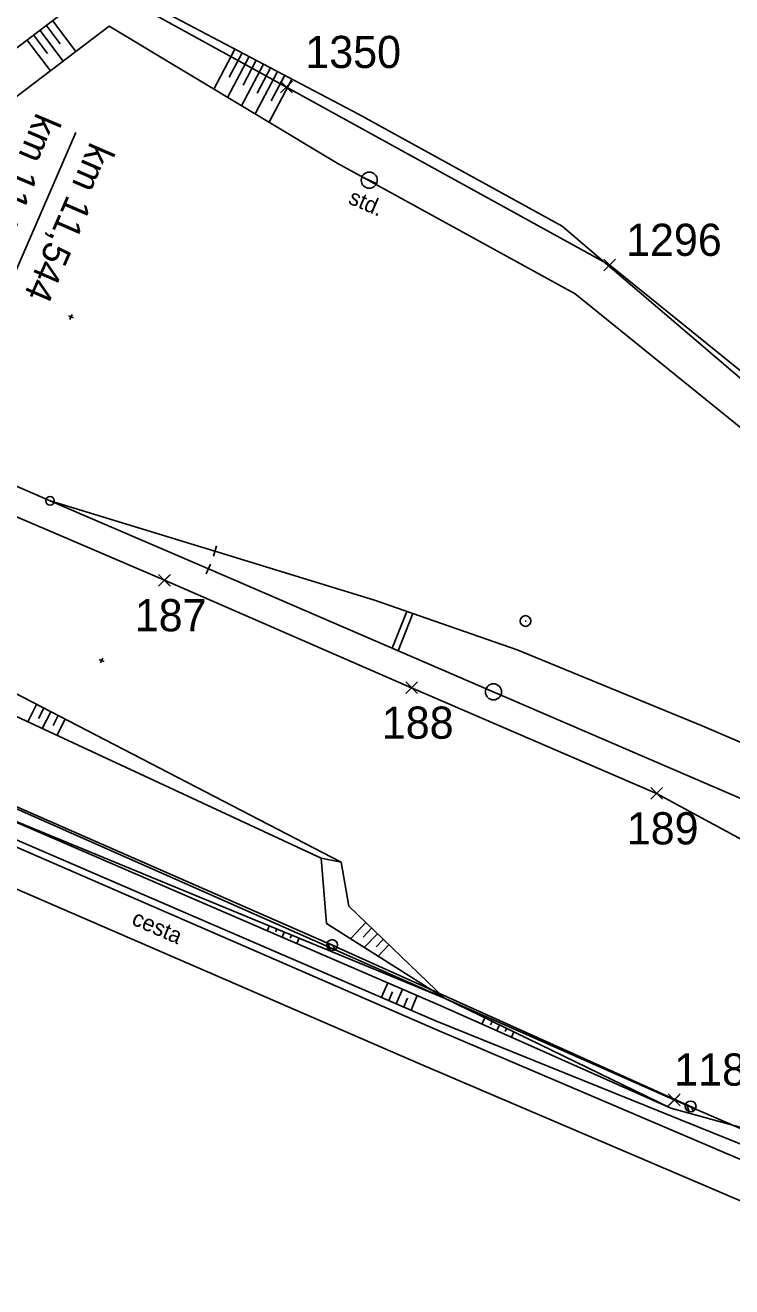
# Model space of a CAD drawing. Extents: x -866402 to -860377, y -1041908 to -1038598.
# Drawn here: x -861070.2 to -861004.3, y -1040160.6 to -1040043.1 of the extents above; entities that cross this region are included whole.
import ezdxf

# ---------------------------------------------------------------- set-up
doc = ezdxf.new("R2010")
doc.units = 0
for name, color, linetype in [('PS 02 trasa', 7, 'Continuous'), ('SZDC', 7, 'Continuous'), ('Vrstva 1', 7, 'Continuous'), ('Vrstva 2', 7, 'Continuous'), ('Vrstva 25', 7, 'Continuous'), ('Vrstva 36', 7, 'Continuous'), ('Vrstva 41', 7, 'Continuous'), ('Vrstva 48', 7, 'Continuous'), ('Vrstva 49', 7, 'Continuous'), ('Vrstva 5', 7, 'Continuous'), ('Vrstva 51', 7, 'Continuous'), ('Vrstva 60', 7, 'Continuous'), ('Vrstva 7', 7, 'Continuous'), ('Vrstva 9', 7, 'Continuous')]:
    doc.layers.add(name, color=color, linetype=linetype)

msp = doc.modelspace()

# ---------------------------------------------------------------- linework, layer by layer
at = {"layer": 'PS 02 trasa'}
msp.add_lwpolyline([(-861275.08, -1039976.7), (-861256.92, -1039992.44), (-861236.93, -1040007.63), (-861216.04, -1040021.56), (-861194.33, -1040033.85), (-861171.81, -1040045.14), (-861147.59, -1040055.88), (-861141.51, -1040058.52), (-861134.42, -1040061.82), (-861125.95, -1040065.2), (-861103.13, -1040075.05), (-861080.22, -1040084.95), (-861057.2, -1040094.8), (-861034.16, -1040104.82), (-861011.32, -1040114.66), (-860987.72, -1040127.44), (-860941.72, -1040147.22), (-860915.57, -1040159.23)], dxfattribs=at)
at = {"layer": 'SZDC'}
for points in [[(-860979.92, -1040156.1), (-861009.68, -1040143.23), (-861085.36, -1040109.77), (-861149.67, -1040082.68), (-861135.92, -1040065.09), (-861147.11, -1040058.58), (-861187.17, -1040040.97), (-861209.35, -1040028.85), (-861227.63, -1040016.54), (-861229.18, -1040015.49), (-861234.59, -1040011.85), (-861236.71, -1040010.09), (-861295.08, -1039961.46)], [(-861261.75, -1039976.4), (-861207.66, -1040016.44), (-861178.07, -1040032.92), (-861123.93, -1040056.86), (-861120.81, -1040053.41), (-861111.29, -1040057.53), (-861106.75, -1040059.49), (-861091.91, -1040065.91), (-861080.02, -1040037.82), (-861096.96, -1040029.84), (-861063.4, -1040039.15), (-861045.83, -1040048.83), (-861015.69, -1040065.42), (-860995.26, -1040081.93), (-860925.73, -1040118.15), (-860902.64, -1040130.18), (-860914.76, -1040137.1), (-860798.14, -1040185.35)]]:
    msp.add_lwpolyline(points, dxfattribs=at)
at = {"layer": 'Vrstva 1'}
msp.add_line((-861067.87, -1040087.39), (-861052.5, -1040092.08), dxfattribs=at)
for points in [[(-861077.48, -1040083.24), (-861076.39, -1040083.71), (-861067.87, -1040087.39), (-861053.11, -1040093.75)], [(-861052.5, -1040092.08), (-861037.62, -1040096.65), (-861024.33, -1040101.3), (-861007.06, -1040108.36), (-860979.17, -1040120.32), (-860937.59, -1040138.29), (-860889.45, -1040159.06)], [(-861053.11, -1040093.75), (-861027.49, -1040104.79), (-860981.18, -1040124.75), (-860939.74, -1040142.64), (-860923.59, -1040149.61), (-860920.27, -1040151.05), (-860891.33, -1040163.55), (-860835.4, -1040187.75)]]:
    msp.add_lwpolyline(points, dxfattribs=at)
at = {"layer": 'Vrstva 2'}
for p, q in [((-861067.87, -1040087.39), (-861052.5, -1040092.08)), ((-861052.35, -1040091.6), (-861052.64, -1040092.56)), ((-861052.91, -1040093.29), (-861053.31, -1040094.21))]:
    msp.add_line(p, q, dxfattribs=at)
msp.add_lwpolyline([(-861077.48, -1040083.24), (-861076.39, -1040083.71), (-861067.87, -1040087.39), (-861053.11, -1040093.75)], dxfattribs=at)
msp.add_circle((-861067.87, -1040087.39), 0.4, dxfattribs=at)
at = {"layer": 'Vrstva 25'}
msp.add_lwpolyline([(-861109.11, -1040099.06), (-861074.55, -1040114.35), (-861041.57, -1040128.8), (-861008.15, -1040143.84)], dxfattribs=at)
at = {"layer": 'Vrstva 36'}
for p, q in [((-861042.03, -1040128.6), (-861041.11, -1040129.01)), ((-861041.11, -1040129.01), (-861042.03, -1040128.6)), ((-861041.72, -1040129.28), (-861041.97, -1040128.63)), ((-861041.33, -1040129.24), (-861041.48, -1040128.84)), ((-861008.61, -1040143.63), (-861007.69, -1040144.05)), ((-861007.69, -1040144.05), (-861008.61, -1040143.63)), ((-861008.29, -1040144.32), (-861008.54, -1040143.66)), ((-861007.91, -1040144.28), (-861008.06, -1040143.88))]:
    msp.add_line(p, q, dxfattribs=at)
for centre in [(-861041.57, -1040128.8), (-861008.15, -1040143.84)]:
    msp.add_circle(centre, 0.503, dxfattribs=at)
for centre in [(-861041.57, -1040128.8), (-861008.15, -1040143.84)]:
    msp.add_arc(centre, 0.503, 155.7777, 335.7777, dxfattribs=at)
at = {"layer": 'Vrstva 41'}
msp.add_line((-861038.8, -1040057.21), (-861037.42, -1040057.81), dxfattribs=at)
msp.add_circle((-861038.11, -1040057.51), 0.752, dxfattribs=at)
at = {"layer": 'Vrstva 48'}
for p, q in [((-861066.64, -1040046.41), (-861068.83, -1040043.53)), ((-861066.92, -1040044.81), (-861068.23, -1040043.08)), ((-861065.45, -1040045.51), (-861067.63, -1040042.63)), ((-861067.84, -1040047.32), (-861070.02, -1040044.44)), ((-861068.11, -1040045.71), (-861069.42, -1040043.98)), ((-861052.6, -1040049.02), (-861050.63, -1040045.29)), ((-861051.31, -1040049.8), (-861049.31, -1040045.99)), ((-861051.16, -1040047.9), (-861049.97, -1040045.64)), ((-861050.03, -1040050.57), (-861047.98, -1040046.69)), ((-861049.86, -1040048.65), (-861048.64, -1040046.34)), ((-861048.56, -1040049.39), (-861047.32, -1040047.04)), ((-861048.74, -1040051.34), (-861046.65, -1040047.39)), ((-861047.45, -1040052.12), (-861045.33, -1040048.09)), ((-861047.25, -1040050.13), (-861045.99, -1040047.74)), ((-861069.95, -1040107.99), (-861069.12, -1040106.38)), ((-861068.95, -1040107.68), (-861068.46, -1040106.73)), ((-861068.59, -1040108.62), (-861067.79, -1040107.07)), ((-861067.59, -1040108.33), (-861067.12, -1040107.42)), ((-861067.23, -1040109.26), (-861066.46, -1040107.76)), ((-861047.61, -1040127.47), (-861047.43, -1040127.02)), ((-861039.86, -1040128.21), (-861038.43, -1040126.71)), ((-861046.85, -1040127.58), (-861046.73, -1040127.31)), ((-861046.23, -1040128.06), (-861046.04, -1040127.59)), ((-861045.47, -1040128.17), (-861045.35, -1040127.88)), ((-861044.86, -1040128.66), (-861044.65, -1040128.16)), ((-861038.68, -1040128.06), (-861037.89, -1040127.23)), ((-861038.57, -1040129.02), (-861037.35, -1040127.75)), ((-861037.47, -1040128.97), (-861036.81, -1040128.27)), ((-861037.28, -1040129.84), (-861036.27, -1040128.79)), ((-861036.38, -1040132.32), (-861036.97, -1040133.67)), ((-861035.01, -1040132.91), (-861035.59, -1040134.27)), ((-861035.93, -1040133.15), (-861036.28, -1040133.97)), ((-861034.55, -1040133.75), (-861034.9, -1040134.56)), ((-861033.63, -1040133.5), (-861034.21, -1040134.86)), ((-861027.6, -1040136.16), (-861027.32, -1040135.59)), ((-861026.81, -1040136.24), (-861026.65, -1040135.91)), ((-861026.23, -1040136.77), (-861025.97, -1040136.24)), ((-861025.45, -1040136.87), (-861025.3, -1040136.57)), ((-861024.86, -1040137.38), (-861024.62, -1040136.9))]:
    msp.add_line(p, q, dxfattribs=at)
at = {"layer": 'Vrstva 49'}
for p, q in [((-861066.15, -1040070.16), (-861065.68, -1040070.35)), ((-861065.82, -1040070.02), (-861066.01, -1040070.49)), ((-861063.29, -1040102.19), (-861062.82, -1040102.37)), ((-861062.96, -1040102.05), (-861063.15, -1040102.51)), ((-861042.58, -1040120.7), (-861040.73, -1040121.06))]:
    msp.add_line(p, q, dxfattribs=at)
for points in [[(-860959.04, -1040117.34), (-860968.02, -1040109.87), (-860976.59, -1040099.98), (-860991.29, -1040086.4), (-861020.11, -1040061.8), (-861039.11, -1040051.37), (-861062.73, -1040038.91), (-861075.26, -1040048.4), (-861085.28, -1040043.96)], [(-861078.58, -1040051.3), (-861074.03, -1040052.02), (-861062.35, -1040043.16), (-861041.11, -1040055.93), (-861018.9, -1040068.11), (-860991.12, -1040090.57), (-860978.75, -1040101.31), (-860969.82, -1040111.55), (-860959.04, -1040117.34)], [(-861120.33, -1040068.92), (-861084.4, -1040085.33), (-861083.29, -1040095), (-861081.74, -1040097.96), (-861076.32, -1040102.66), (-861040.73, -1040121.06), (-861040.02, -1040125.18), (-861031.11, -1040133.74)], [(-861120.78, -1040070.75), (-861087.76, -1040086.41), (-861084.95, -1040095.8), (-861083.19, -1040098.55), (-861076.84, -1040104.79), (-861042.58, -1040120.7), (-861042.09, -1040126.8), (-861031.11, -1040133.74)], [(-861031.51, -1040134.42), (-861074.82, -1040115.73), (-861091.17, -1040108.85), (-861129.46, -1040091.95)], [(-861130.45, -1040093.32), (-861091.83, -1040109.9), (-861075.06, -1040117.25), (-861031.99, -1040135.82)], [(-861031.11, -1040133.74), (-861074.82, -1040115.73)], [(-861031.11, -1040133.74), (-861010, -1040144.01)], [(-861031.51, -1040134.42), (-861010, -1040144.01)], [(-860995.4, -1040150.62), (-861031.99, -1040135.82)], [(-860982.69, -1040140.43), (-860985.23, -1040142.72), (-860990.35, -1040149.03), (-860994.6, -1040148.22), (-861010, -1040144.01)]]:
    msp.add_lwpolyline(points, dxfattribs=at)
at = {"layer": 'Vrstva 51'}
for points in [[(-860938.23, -1040177.64), (-860956.08, -1040169.01), (-861031.95, -1040136.63), (-861076.08, -1040117.48), (-861093.57, -1040110.16), (-861130.72, -1040094.12)], [(-861132.07, -1040097.36), (-861095.52, -1040113.25), (-861077.51, -1040120.75), (-861033.32, -1040139.9), (-860957.23, -1040172.41), (-860939.95, -1040180.98)]]:
    msp.add_lwpolyline(points, dxfattribs=at)
at = {"layer": 'Vrstva 60'}
for p, q in [((-861045.38, -1040049.28), (-861046.38, -1040048.28)), ((-861045.38, -1040048.38), (-861046.38, -1040049.38)), ((-861046.28, -1040049.28), (-861045.28, -1040048.28)), ((-861046.28, -1040048.38), (-861045.28, -1040049.38)), ((-861045.83, -1040048.83), (-861045.83, -1040048.83)), ((-861015.24, -1040065.87), (-861016.24, -1040064.87)), ((-861015.24, -1040064.97), (-861016.24, -1040065.97)), ((-861016.14, -1040065.87), (-861015.14, -1040064.87)), ((-861016.14, -1040064.97), (-861015.14, -1040065.97)), ((-861015.69, -1040065.42), (-861015.69, -1040065.42)), ((-861056.75, -1040095.25), (-861057.75, -1040094.25)), ((-861057.65, -1040095.25), (-861056.65, -1040094.25)), ((-861056.75, -1040094.35), (-861057.75, -1040095.35)), ((-861057.65, -1040094.35), (-861056.65, -1040095.35)), ((-861057.2, -1040094.8), (-861057.2, -1040094.8)), ((-861033.71, -1040105.27), (-861034.71, -1040104.27)), ((-861033.71, -1040104.37), (-861034.71, -1040105.37)), ((-861034.61, -1040105.27), (-861033.61, -1040104.27)), ((-861034.61, -1040104.37), (-861033.61, -1040105.37)), ((-861034.16, -1040104.82), (-861034.16, -1040104.82)), ((-861010.87, -1040115.11), (-861011.87, -1040114.11)), ((-861010.87, -1040114.21), (-861011.87, -1040115.21)), ((-861011.77, -1040115.11), (-861010.77, -1040114.11)), ((-861011.77, -1040114.21), (-861010.77, -1040115.21)), ((-861011.32, -1040114.66), (-861011.32, -1040114.66)), ((-861009.23, -1040143.68), (-861010.23, -1040142.68)), ((-861009.23, -1040142.78), (-861010.23, -1040143.78)), ((-861010.13, -1040143.68), (-861009.13, -1040142.68)), ((-861010.13, -1040142.78), (-861009.13, -1040143.78)), ((-861009.68, -1040143.23), (-861009.68, -1040143.23))]:
    msp.add_line(p, q, dxfattribs=at)
at = {"layer": 'Vrstva 7'}
for p, q in [((-861035.96, -1040101.14), (-861034.62, -1040097.7)), ((-861035.41, -1040101.38), (-861034.05, -1040097.9)), ((-861023.58, -1040098.6), (-861023.48, -1040098.6))]:
    msp.add_line(p, q, dxfattribs=at)
for centre, radius in [((-861023.54, -1040098.6), 0.5), ((-861026.53, -1040105.2), 0.75)]:
    msp.add_circle(centre, radius, dxfattribs=at)
at = {"layer": 'Vrstva 9'}
msp.add_line((-861077.11, -1040079.9), (-861065.47, -1040053.06), dxfattribs=at)

# ---------------------------------------------------------------- texts
at = {"layer": 'Vrstva 41'}
msp.add_text('std.', height=1.5, rotation=336.693, dxfattribs=at).set_placement((-861040.16, -1040059.65))
at = {"layer": 'Vrstva 5'}
msp.add_text('km 11,539', height=2.5, rotation=247.0634, dxfattribs=at).set_placement((-861069.12, -1040051.12))
at = {"layer": 'Vrstva 51'}
msp.add_text('cesta', height=1.5, rotation=336.5707, dxfattribs=at).set_placement((-861060.36, -1040126.84))
at = {"layer": 'Vrstva 60'}
for s, p in [('1350', (-861044.07, -1040047.06)), ('1296', (-861014.17, -1040064.57)), ('187', (-861059.97, -1040099.56)), ('188', (-861036.94, -1040109.57)), ('189', (-861014.1, -1040119.42)), ('1188', (-861009.68, -1040141.9))]:
    msp.add_text(s, height=3, dxfattribs=at).set_placement(p)
at = {"layer": 'Vrstva 9'}
msp.add_text('km 11,544', height=2.5, rotation=246.5547, dxfattribs=at).set_placement((-861064.1, -1040053.85))

doc.saveas('drawing.dxf')
